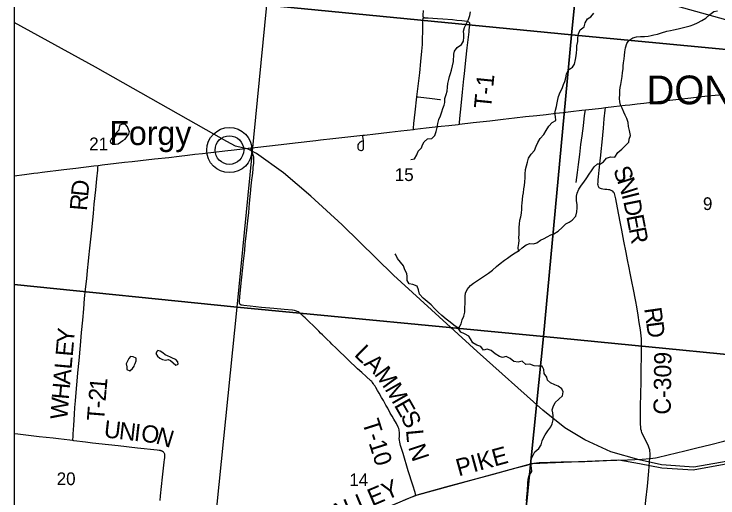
# Model space of a CAD drawing. Extents: x 831 to 1552, y 430 to 870.
# Drawn here: x 1250.77 to 1297.11, y 696.04 to 727.92 of the extents above; entities that cross this region are included whole.
import ezdxf

# ---------------------------------------------------------------- set-up
doc = ezdxf.new("R2010")
doc.units = 0
for name, color, linetype in [('GM_X_Corporation', 7, 'Continuous'), ('GM_X_Corporation_Text', 7, 'Continuous'), ('GM_X_County_Road', 7, 'Continuous'), ('GM_X_County_Road_Text', 7, 'Continuous'), ('GM_X_Minor_Lake', 7, 'Continuous'), ('GM_X_Minor_River', 7, 'Continuous'), ('GM_X_Rail_Line', 7, 'Continuous'), ('GM_X_Section_Text', 7, 'Continuous'), ('GM_X_Township_Road', 7, 'Continuous'), ('GM_X_Township_Road_Text', 7, 'Continuous'), ('GM_X_Unincorporated', 7, 'Continuous'), ('GM_X_Unincorporated_Location', 7, 'Continuous'), ('GM_X_Unincorporated_Text', 7, 'Continuous'), ('GM_X_US_Route', 7, 'Continuous'), ('SH_Text', 7, 'Continuous')]:
    doc.layers.add(name, color=color, linetype=linetype)

msp = doc.modelspace()

# ---------------------------------------------------------------- linework, layer by layer
at = {"layer": 'GM_X_Corporation'}
msp.add_lwpolyline([(1250.766, 771.115), (1250.766, 667.013)], dxfattribs=at)
for points in [[(1269.535, 749.022), (1289.554, 747.22), (1287.469, 726.554), (1267.407, 728.501)], [(1289.554, 747.22), (1309.391, 745.383), (1307.365, 724.655), (1287.469, 726.554)], [(1250.766, 730.422), (1250.766, 710.102), (1265.456, 708.606), (1267.407, 728.501)], [(1267.407, 728.501), (1287.469, 726.554), (1285.616, 706.68), (1265.456, 708.606)], [(1287.469, 726.554), (1307.365, 724.655), (1305.299, 704.746), (1285.616, 706.68)], [(1250.766, 710.102), (1250.766, 689.618), (1263.383, 688.281), (1265.456, 708.606)], [(1265.456, 708.606), (1285.616, 706.68), (1283.584, 686.544), (1263.383, 688.281)], [(1305.299, 704.746), (1303.37, 684.858), (1283.584, 686.544), (1285.616, 706.68)]]:
    msp.add_lwpolyline(points, close=True, dxfattribs=at)
at = {"layer": 'GM_X_County_Road'}
for points in [[(1292.633, 698.634), (1292.643, 698.745), (1292.641, 698.969), (1292.624, 699.153), (1292.614, 699.213), (1292.583, 699.33), (1292.541, 699.445), (1292.464, 699.613), (1292.324, 699.89), (1292.183, 700.167), (1292.108, 700.339), (1292.068, 700.458), (1292.039, 700.581), (1292.021, 700.706), (1292.007, 700.893), (1292.006, 701.143), (1292.018, 701.889), (1292.037, 703.071), (1292.046, 703.506), (1292.051, 704.128), (1292.06, 704.626), (1292.068, 705.246), (1292.072, 705.675), (1292.084, 706.106), (1292.068, 706.512), (1292.053, 706.719), (1292.002, 707.125), (1291.932, 707.589), (1291.856, 708.077), (1291.771, 708.642), (1291.709, 708.976), (1291.521, 709.889), (1291.458, 710.189), (1291.323, 710.844), (1291.256, 711.205), (1291.155, 711.737), (1291.065, 712.219), (1290.911, 712.967), (1290.775, 713.683), (1290.67, 714.233), (1290.489, 715.163), (1290.381, 715.749), (1290.329, 716.017), (1290.305, 716.097), (1290.279, 716.146), (1290.241, 716.194), (1290.179, 716.247), (1290.122, 716.281), (1290.043, 716.313), (1289.986, 716.33), (1289.905, 716.345), (1289.797, 716.359), (1289.656, 716.369), (1289.534, 716.386), (1289.433, 716.411), (1289.367, 716.432), (1289.297, 716.477), (1289.242, 716.557), (1289.214, 716.637), (1289.207, 716.721), (1289.214, 716.854), (1289.228, 716.99), (1289.249, 717.192), (1289.269, 717.411), (1289.289, 717.637), (1289.355, 718.243), (1289.392, 718.621), (1289.415, 718.861), (1289.478, 719.479), (1289.567, 720.408), (1289.625, 721.027), (1289.68, 721.584), (1289.697, 721.76)], [(1292.633, 698.634), (1292.832, 698.659), (1293.002, 698.688), (1293.111, 698.71), (1293.836, 698.882), (1294.929, 699.15), (1295.727, 699.34), (1296.648, 699.564), (1297.492, 699.772), (1298.005, 699.907), (1298.324, 700.001), (1298.721, 700.132), (1300.531, 700.794), (1301.831, 701.285), (1302.769, 701.643), (1303.599, 701.948), (1304.36, 702.232), (1305.159, 702.509)], [(1277.227, 696.204), (1277.316, 696.238), (1277.703, 696.356), (1279.193, 696.763), (1280.741, 697.188), (1282.234, 697.593), (1283.819, 698.019), (1284.447, 698.185), (1284.764, 698.269), (1285.018, 698.323), (1285.168, 698.344), (1285.342, 698.364), (1286.793, 698.409), (1287.917, 698.443), (1288.342, 698.451), (1289.764, 698.499), (1291.153, 698.547), (1292.125, 698.592), (1292.633, 698.634)], [(1261.024, 687.746), (1261.052, 687.764), (1261.356, 687.956), (1263.589, 689.303), (1264.173, 689.657), (1264.599, 689.912), (1266.889, 691.283), (1267.798, 691.821), (1268.765, 692.395), (1269.721, 692.957), (1270.11, 693.177), (1270.355, 693.302), (1270.714, 693.465), (1271.511, 693.812), (1273.397, 694.61), (1274.483, 695.072), (1276.029, 695.719), (1276.702, 695.999), (1276.91, 696.084), (1277.227, 696.204)]]:
    msp.add_lwpolyline(points, dxfattribs=at)
at = {"layer": 'GM_X_Minor_Lake'}
for points in [[(1258.33, 720.254), (1258.23, 720.496), (1258.095, 720.634), (1257.913, 720.659), (1257.73, 720.593), (1257.675, 720.442), (1257.657, 720.282), (1257.519, 720.109), (1257.463, 719.935), (1257.347, 719.785), (1257.172, 719.726), (1257.094, 719.552)], [(1257.094, 719.552), (1257.116, 719.469), (1257.281, 719.353), (1257.448, 719.358), (1257.616, 719.379), (1257.769, 719.491), (1257.922, 719.581), (1258.091, 719.677), (1258.199, 719.836), (1258.33, 720.009), (1258.363, 720.175), (1258.33, 720.254)], [(1258.794, 705.257), (1258.605, 705.343), (1258.438, 705.367), (1258.33, 705.217), (1258.237, 705.051), (1258.144, 704.87), (1258.187, 704.679), (1258.192, 704.497), (1258.389, 704.419), (1258.573, 704.561), (1258.666, 704.727), (1258.698, 704.811)], [(1260.182, 705.712), (1260.097, 705.561), (1260.209, 705.385), (1260.359, 705.246), (1260.548, 705.153), (1260.73, 705.128), (1260.912, 705.156), (1261.071, 705.094), (1261.417, 704.786), (1261.518, 704.83)], [(1261.518, 704.83), (1261.57, 704.852), (1261.549, 705.012), (1261.414, 705.158), (1261.247, 705.228), (1261.059, 705.306), (1260.87, 705.4), (1260.711, 705.462), (1260.561, 705.601), (1260.38, 705.702), (1260.221, 705.757), (1260.182, 705.712)], [(1258.698, 704.811), (1258.729, 704.893), (1258.799, 705.067), (1258.794, 705.257)]]:
    msp.add_lwpolyline(points, dxfattribs=at)
at = {"layer": 'GM_X_Minor_River'}
for points in [[(1279.635, 724.514), (1279.707, 724.794), (1279.713, 725.272), (1279.753, 725.477), (1279.939, 725.718), (1280.222, 725.92), (1280.362, 726.146), (1280.38, 726.404), (1280.368, 726.594), (1280.355, 726.791), (1280.426, 727.041), (1280.567, 727.351), (1280.676, 727.57), (1280.77, 727.827), (1280.819, 728.062)], [(1293.398, 726.677), (1293.741, 726.787), (1293.985, 726.837), (1294.176, 726.888), (1294.488, 726.937), (1294.747, 727.003), (1295.021, 727.076), (1295.288, 727.156), (1295.525, 727.237), (1295.769, 727.348), (1296.045, 727.489), (1296.32, 727.66), (1296.581, 727.893), (1296.835, 728.087), (1297.078, 728.13)], [(1283.987, 712.327), (1283.962, 712.533), (1284.01, 712.798), (1284.013, 712.995), (1284.008, 713.208), (1284.018, 713.398), (1284.013, 713.648), (1284.024, 713.891), (1284.042, 714.088), (1284.075, 714.331), (1284.123, 714.558), (1284.164, 714.801), (1284.191, 715.074), (1284.201, 715.279), (1284.211, 715.469), (1284.236, 715.704), (1284.262, 715.946), (1284.302, 716.143), (1284.336, 716.416), (1284.369, 716.636), (1284.387, 716.871), (1284.406, 717.137), (1284.416, 717.372), (1284.443, 717.676), (1284.571, 718.16), (1284.627, 718.433), (1284.813, 718.681), (1285.021, 718.937), (1285.146, 719.224), (1285.248, 719.458), (1285.403, 719.715), (1285.641, 719.978), (1285.797, 720.242), (1285.975, 720.536), (1286.198, 720.769), (1286.436, 720.918), (1286.408, 721.176), (1286.365, 721.367), (1286.406, 721.579), (1286.47, 721.836), (1286.518, 722.064), (1286.574, 722.291), (1286.615, 722.495), (1286.725, 722.775), (1286.842, 723.024), (1286.944, 723.274), (1287.022, 723.47), (1287.101, 723.72), (1287.135, 723.978), (1287.275, 724.242), (1287.543, 724.414), (1287.667, 724.61), (1287.739, 724.92), (1287.772, 725.17), (1287.798, 725.375), (1287.808, 725.588), (1287.826, 725.838), (1287.875, 726.111), (1287.893, 726.346), (1287.927, 726.627), (1288.044, 726.876), (1288.298, 727.071), (1288.377, 727.343), (1288.517, 727.6), (1288.747, 727.742), (1288.932, 727.99)], [(1280.022, 707.209), (1280.207, 707.504), (1280.279, 707.769), (1280.381, 708.026), (1280.452, 708.276), (1280.448, 708.557), (1280.46, 708.868), (1280.47, 709.111), (1280.465, 709.324), (1280.491, 709.528), (1280.592, 709.77), (1280.808, 710.041), (1281.015, 710.183), (1281.276, 710.377), (1281.475, 710.504), (1281.743, 710.668), (1281.996, 710.84), (1282.264, 711.049), (1282.525, 711.281), (1282.771, 711.491), (1283.047, 711.708), (1283.262, 711.827), (1283.507, 712.029), (1283.76, 712.193), (1284.012, 712.342), (1284.212, 712.522), (1284.473, 712.717), (1284.717, 712.797), (1284.975, 712.787), (1285.181, 712.853), (1285.419, 713.017), (1285.663, 713.135), (1285.87, 713.239), (1286.114, 713.373), (1286.305, 713.439), (1286.596, 713.626), (1286.85, 713.866), (1287.096, 714.106), (1287.31, 714.217), (1287.517, 714.344), (1287.748, 714.607), (1287.812, 714.887), (1287.838, 715.16), (1287.833, 715.358), (1287.806, 715.631), (1287.802, 715.912), (1287.835, 716.117), (1287.952, 716.389), (1288.115, 716.645), (1288.277, 716.841), (1288.47, 717.12), (1288.625, 717.368), (1288.773, 717.602), (1288.966, 717.866), (1289.181, 718.061), (1289.378, 718.058), (1289.57, 718.185), (1289.778, 718.433), (1290.037, 718.506), (1290.311, 718.503), (1290.512, 718.789), (1290.773, 719.022), (1291.019, 719.269), (1291.235, 719.487), (1291.26, 719.684), (1291.354, 719.918), (1291.29, 720.246), (1291.217, 720.52), (1291.197, 720.771), (1291.117, 721.038), (1291.006, 721.252), (1290.917, 721.458), (1290.799, 721.71), (1290.703, 721.946), (1290.652, 722.144), (1290.624, 722.35), (1290.643, 722.638), (1290.654, 722.889), (1290.672, 723.093), (1290.712, 723.283), (1290.761, 723.533), (1290.794, 723.806), (1290.821, 724.071), (1290.862, 724.322), (1290.879, 724.511), (1290.897, 724.716), (1290.931, 724.982), (1290.964, 725.186), (1290.989, 725.437), (1291.031, 725.702), (1291.118, 725.974), (1291.242, 726.17), (1291.51, 726.365), (1291.746, 726.43), (1292.013, 726.45), (1292.278, 726.432), (1292.514, 726.459), (1292.705, 726.51), (1292.895, 726.546), (1293.139, 726.596), (1293.398, 726.677)], [(1276.892, 718.341), (1277.121, 718.392), (1277.283, 718.64), (1277.378, 718.897), (1277.593, 719.107), (1277.656, 719.304), (1277.765, 719.5), (1277.995, 719.703), (1278.261, 719.73), (1278.469, 719.91), (1278.563, 720.182), (1278.62, 720.455), (1278.661, 720.705), (1278.74, 720.97), (1278.834, 721.212), (1278.921, 721.484), (1279, 721.696), (1279.079, 721.915), (1279.119, 722.105), (1279.122, 722.363), (1279.217, 722.627), (1279.288, 722.832), (1279.306, 723.097), (1279.324, 723.34), (1279.388, 723.605), (1279.444, 723.802), (1279.507, 723.999), (1279.556, 724.226), (1279.635, 724.514)], [(1285.529, 704.724), (1285.286, 704.719), (1285.005, 704.745), (1284.725, 704.862), (1284.467, 704.842), (1284.219, 705.043), (1283.952, 704.985), (1283.664, 705.026), (1283.423, 705.234), (1283.167, 705.359), (1282.915, 705.286), (1282.718, 705.349), (1282.447, 705.542), (1282.176, 705.75), (1281.919, 705.837), (1281.683, 705.771), (1281.488, 706.024), (1281.231, 706.103), (1280.974, 706.258), (1280.811, 706.518), (1280.707, 706.709), (1280.427, 706.849), (1280.178, 706.966), (1280.007, 707.233), (1279.728, 707.434), (1279.479, 707.612), (1279.216, 707.82), (1278.923, 708.051), (1278.682, 708.289), (1278.465, 708.504), (1278.217, 708.765), (1277.969, 708.988), (1277.691, 709.212), (1277.466, 709.465), (1277.386, 709.755), (1277.298, 709.991), (1277.026, 710.093), (1276.776, 710.149), (1276.649, 710.371), (1276.652, 710.621), (1276.624, 710.819), (1276.498, 711.071), (1276.41, 711.323), (1276.201, 711.568), (1276.006, 711.821), (1275.895, 712.065), (1275.864, 712.119)], [(1284.508, 695.852), (1284.534, 696.11), (1284.552, 696.33), (1284.577, 696.534), (1284.583, 696.997), (1284.624, 697.278), (1284.681, 697.513), (1284.851, 697.776), (1284.839, 698.027), (1284.781, 698.278), (1284.8, 698.551), (1284.924, 698.808), (1285.057, 699.087), (1285.325, 699.289), (1285.465, 699.538), (1285.537, 699.803), (1285.63, 700), (1285.739, 700.203), (1285.917, 700.467), (1286.103, 700.723), (1286.204, 700.919), (1286.268, 701.184), (1286.256, 701.442), (1286.228, 701.64), (1286.2, 701.838), (1286.256, 702.035), (1286.396, 702.329), (1286.627, 702.554), (1286.872, 702.772), (1286.929, 703.037), (1286.84, 703.228), (1286.599, 703.413), (1286.38, 703.499), (1286.093, 703.624), (1285.882, 703.808), (1285.839, 704.006), (1285.675, 704.228), (1285.64, 704.494), (1285.529, 704.724)]]:
    msp.add_lwpolyline(points, dxfattribs=at)
at = {"layer": 'GM_X_Rail_Line'}
for points in [[(1298.165, 698.538), (1295.52, 698.073), (1293.393, 698.231), (1291.914, 698.547), (1290.066, 699.084), (1288.334, 699.86), (1287.035, 700.657), (1285.578, 701.832), (1281.266, 705.686), (1275.746, 710.712), (1272.364, 714.04), (1270.301, 715.92), (1268.501, 717.45), (1266.727, 718.726), (1266.168, 719.011), (1265.343, 719.228), (1264.784, 719.514), (1263.408, 720.296), (1256.132, 724.433), (1250.766, 727.368)], [(1250.766, 679.957), (1255.444, 683.813), (1257.495, 685.358), (1259.895, 687.02), (1261.608, 688.118), (1265.466, 690.461), (1268.571, 692.318), (1270.198, 693.26), (1277.176, 696.209), (1284.864, 698.305), (1290.582, 698.552), (1291.934, 698.299), (1293.404, 698.016), (1295.482, 697.897), (1297.508, 698.271), (1299.512, 698.644), (1302.371, 699.157), (1309.027, 700.546), (1335.38, 705.567), (1347.114, 707.619), (1348.184, 707.837)]]:
    msp.add_lwpolyline(points, dxfattribs=at)
at = {"layer": 'GM_X_Township_Road'}
for points in [[(1277.735, 727.69), (1277.718, 727.709), (1277.703, 727.732), (1277.695, 727.758), (1277.692, 727.786), (1277.693, 727.846), (1277.716, 728.153)], [(1277.294, 722.466), (1277.334, 722.819), (1277.472, 724.056), (1277.548, 724.799), (1277.614, 725.48), (1277.651, 725.914), (1277.666, 726.224), (1277.677, 726.846), (1277.683, 727.406), (1277.689, 727.548), (1277.706, 727.619), (1277.735, 727.69)], [(1280.092, 720.666), (1280.099, 720.755), (1280.122, 721.048), (1280.202, 721.877), (1280.288, 722.78), (1280.384, 723.644), (1280.421, 723.991), (1280.508, 724.878), (1280.602, 725.701), (1280.722, 726.755), (1280.739, 726.889), (1280.767, 727.186), (1280.771, 727.256), (1280.77, 727.287), (1280.765, 727.317), (1280.751, 727.345), (1280.733, 727.369), (1280.707, 727.39), (1280.671, 727.409), (1280.582, 727.429), (1280.422, 727.453), (1280.243, 727.476), (1279.922, 727.506), (1279.625, 727.536), (1279.006, 727.579), (1278.636, 727.607), (1278.336, 727.627), (1278.026, 727.651), (1277.839, 727.658), (1277.808, 727.661), (1277.781, 727.667), (1277.735, 727.69)], [(1277.055, 720.321), (1277.064, 720.411), (1277.094, 720.716), (1277.18, 721.459), (1277.294, 722.466)], [(1277.294, 722.466), (1277.38, 722.457), (1278.3, 722.357), (1278.789, 722.293), (1278.849, 722.284)], [(1287.776, 716.82), (1287.86, 717.493), (1287.926, 718.008), (1288.01, 718.666), (1288.09, 719.336), (1288.163, 719.895), (1288.248, 720.566), (1288.332, 721.243), (1288.365, 721.489), (1288.381, 721.605)], [(1273.749, 719.564), (1273.642, 719.522), (1273.577, 719.489), (1273.518, 719.454), (1273.477, 719.418), (1273.436, 719.369), (1273.408, 719.312), (1273.396, 719.257), (1273.389, 719.198), (1273.39, 719.138), (1273.405, 719.083), (1273.424, 719.038), (1273.45, 719.004), (1273.488, 718.974), (1273.539, 718.949), (1273.586, 718.941), (1273.646, 718.939), (1273.703, 718.96), (1273.748, 719.001), (1273.774, 719.056), (1273.78, 719.117), (1273.782, 719.244), (1273.777, 719.296), (1273.765, 719.597), (1273.756, 719.717), (1273.738, 719.849), (1273.727, 719.937)], [(1277.227, 696.204), (1277.164, 696.407), (1277.017, 696.882), (1276.722, 697.832), (1276.38, 698.963), (1276.215, 699.498), (1276.156, 699.709), (1276.134, 699.857), (1276.131, 699.954), (1276.136, 700.062), (1276.145, 700.227), (1276.139, 700.384), (1276.128, 700.469), (1276.116, 700.538), (1276.094, 700.623), (1276.065, 700.703), (1275.945, 700.934), (1275.763, 701.236), (1275.666, 701.418), (1275.538, 701.634), (1275.364, 701.948), (1275.242, 702.162), (1275.082, 702.452), (1274.966, 702.651), (1274.806, 702.936), (1274.701, 703.116), (1274.581, 703.318), (1274.53, 703.409), (1274.484, 703.48), (1274.439, 703.548), (1274.348, 703.663), (1274.31, 703.705), (1274.256, 703.762), (1273.94, 704.049), (1273.662, 704.297), (1273.385, 704.547), (1273.203, 704.716), (1272.942, 704.973), (1272.544, 705.358), (1272.195, 705.695), (1272.128, 705.759), (1272.04, 705.844), (1271.976, 705.906), (1271.694, 706.178), (1271.569, 706.297), (1271.374, 706.488), (1271.07, 706.783), (1270.952, 706.902), (1270.827, 707.027), (1270.426, 707.415), (1270.249, 707.592), (1269.921, 707.91), (1269.824, 708.001), (1269.729, 708.086), (1269.585, 708.223), (1269.53, 708.266), (1269.47, 708.302), (1269.413, 708.33), (1269.354, 708.353), (1269.293, 708.371), (1269.232, 708.385), (1269.108, 708.405), (1268.55, 708.46), (1267.868, 708.523), (1267.063, 708.595), (1266.32, 708.666), (1265.895, 708.71), (1265.776, 708.731), (1265.72, 708.747), (1265.671, 708.776), (1265.635, 708.816), (1265.61, 708.864), (1265.604, 708.921), (1265.607, 708.979), (1265.632, 709.288), (1265.703, 709.968), (1265.768, 710.586), (1265.834, 711.204), (1265.875, 711.637), (1265.95, 712.351), (1265.992, 712.75), (1266.028, 713.122), (1266.09, 713.678), (1266.151, 714.297), (1266.212, 714.853), (1266.275, 715.471), (1266.339, 716.089), (1266.386, 716.609), (1266.428, 717.008), (1266.454, 717.262), (1266.497, 717.686), (1266.517, 717.84), (1266.544, 718.068), (1266.553, 718.192), (1266.56, 718.316), (1266.56, 718.379), (1266.555, 718.443), (1266.545, 718.505), (1266.53, 718.567), (1266.492, 718.687), (1266.408, 718.92), (1266.369, 719.039), (1266.346, 719.106)], [(1254.635, 699.814), (1254.638, 699.88), (1254.646, 700.069), (1254.659, 700.233), (1254.68, 700.544), (1254.697, 700.813), (1254.718, 701.196), (1254.739, 701.57), (1254.768, 701.991), (1254.809, 702.436), (1254.876, 703.24), (1254.918, 703.735), (1254.967, 704.292), (1255.043, 705.095), (1255.135, 706.084), (1255.213, 706.949), (1255.286, 707.753), (1255.353, 708.494), (1255.411, 709.174), (1255.473, 709.792), (1255.546, 710.471), (1255.607, 711.026), (1255.669, 711.642), (1255.693, 711.889), (1255.761, 712.506), (1255.863, 713.492), (1255.988, 714.789), (1256.045, 715.406), (1256.14, 716.332), (1256.211, 717.074), (1256.271, 717.629), (1256.29, 717.814), (1256.305, 717.953)], [(1254.635, 699.814), (1254.44, 699.838), (1253.684, 699.928), (1253.33, 699.97), (1252.424, 700.075), (1251.711, 700.155), (1251.008, 700.237), (1250.766, 700.266)], [(1260.381, 695.879), (1260.416, 696.178), (1260.546, 697.414), (1260.657, 698.405), (1260.677, 698.575), (1260.688, 698.677), (1260.691, 698.711), (1260.696, 698.786), (1260.696, 698.818), (1260.694, 698.869), (1260.688, 698.903), (1260.682, 698.934), (1260.674, 698.958), (1260.655, 698.996), (1260.634, 699.026), (1260.617, 699.048), (1260.588, 699.076), (1260.567, 699.092), (1260.538, 699.109), (1260.518, 699.119), (1260.499, 699.128), (1260.47, 699.139), (1260.436, 699.148), (1260.398, 699.156), (1260.352, 699.164), (1260.314, 699.17), (1260.184, 699.189), (1258.891, 699.322), (1257.619, 699.462), (1256.981, 699.538), (1255.919, 699.657), (1255.469, 699.712), (1254.701, 699.806), (1254.635, 699.814)], [(1290.94, 680.602), (1290.959, 681.116), (1291.008, 681.922), (1291.041, 682.355), (1291.127, 683.282), (1291.209, 684.147), (1291.272, 684.828), (1291.334, 685.445), (1291.393, 686.001), (1291.437, 686.433), (1291.548, 687.483), (1291.653, 688.658), (1291.699, 689.153), (1291.802, 690.266), (1291.952, 691.749), (1292.277, 694.962), (1292.37, 695.889), (1292.462, 696.816), (1292.555, 697.805), (1292.607, 698.423), (1292.633, 698.634)]]:
    msp.add_lwpolyline(points, dxfattribs=at)
at = {"layer": 'GM_X_Unincorporated'}
for radius in [1.488, 0.943]:
    msp.add_circle((1264.941, 718.96), radius, dxfattribs=at)
at = {"layer": 'GM_X_Unincorporated_Location'}
msp.add_line((1264.941, 718.96), (1264.941, 718.96), dxfattribs=at)
at = {"layer": 'GM_X_US_Route'}
for points in [[(1266.346, 719.106), (1266.625, 719.138), (1268.355, 719.328), (1269.281, 719.435), (1270.639, 719.588), (1270.948, 719.626), (1271.75, 719.72), (1272.738, 719.832), (1273.727, 719.937), (1273.835, 719.95), (1274.007, 719.972), (1274.378, 720.015), (1275.489, 720.146), (1276.231, 720.227), (1277.055, 720.321), (1277.158, 720.333), (1277.899, 720.418), (1278.887, 720.535), (1279.382, 720.586), (1280, 720.655), (1280.092, 720.666), (1280.988, 720.771), (1282.1, 720.897), (1282.964, 720.998), (1283.706, 721.082), (1284.447, 721.165), (1285.189, 721.244), (1285.807, 721.313), (1286.425, 721.387), (1286.918, 721.443), (1287.413, 721.499), (1288.154, 721.582), (1288.381, 721.605), (1288.834, 721.652), (1289.451, 721.73), (1289.697, 721.76), (1290.254, 721.826), (1290.995, 721.908), (1291.304, 721.942), (1291.798, 721.998), (1292.231, 722.049), (1292.724, 722.108), (1293.343, 722.174), (1294.33, 722.291), (1295.319, 722.401), (1296.431, 722.528), (1297.421, 722.632)], [(1257.483, 718.093), (1258.043, 718.16), (1258.537, 718.215), (1259.094, 718.27), (1260.02, 718.382), (1260.946, 718.48), (1261.625, 718.565), (1262.18, 718.626), (1262.675, 718.68), (1263.169, 718.736), (1263.889, 718.819)], [(1263.889, 718.819), (1263.909, 718.821), (1264.65, 718.905), (1265.267, 718.98), (1266.346, 719.106)], [(1252.338, 717.463), (1252.615, 717.497), (1254.034, 717.672), (1254.835, 717.774), (1256.007, 717.918), (1256.305, 717.953)], [(1256.305, 717.953), (1256.562, 717.983), (1257.483, 718.093)], [(1250.766, 717.266), (1251.444, 717.352), (1252.061, 717.429), (1252.338, 717.463)]]:
    msp.add_lwpolyline(points, dxfattribs=at)
at = {"layer": 'SH_Text'}
msp.add_lwpolyline([(1309.717, 724.179), (1213.915, 750.822), (1213.915, 760.257)], close=True, dxfattribs=at)

# ---------------------------------------------------------------- texts
at = {"layer": 'GM_X_Corporation_Text'}
msp.add_text('DONNELSVILLE', height=1.89394, rotation=0, dxfattribs=at).set_placement((1292.409, 721.976))
at = {"layer": 'GM_X_County_Road_Text'}
for s, height, rotation, p in [('S', 1.136, 291.0126, (1290.188, 717.654)), ('N', 1.136, 288.0289, (1290.457, 716.953)), ('I', 1.136, 284.1148, (1290.761, 716.021)), ('D', 1.136, 281.3746, (1290.872, 715.583)), ('E', 1.136, 280.9826, (1291.069, 714.605)), ('R', 1.136, 280.9797, (1291.23, 713.77)), ('R', 1.136, 278.1969, (1292.246, 708.522)), ('D', 1.136, 277.6507, (1292.379, 707.601)), ('C-309', 1.1364, 89.1905, (1293.995, 701.52)), ('PIKE', 1.1364, 15.3088, (1280.037, 697.457)), ('VALLEY', 1.1364, 22.8831, (1270.911, 694.036))]:
    msp.add_text(s, height=height, rotation=rotation, dxfattribs=at).set_placement(p)
at = {"layer": 'GM_X_Section_Text'}
for s, height, p in [('21', 0.8371, (1255.712, 718.949)), ('15', 0.8371, (1275.829, 716.92)), ('9', 0.837, (1296.121, 715.01)), ('20', 0.8371, (1253.571, 696.885)), ('14', 0.8371, (1272.837, 696.816))]:
    msp.add_text(s, height=height, rotation=0, dxfattribs=at).set_placement(p)
at = {"layer": 'GM_X_Township_Road_Text'}
for s, height, rotation, p in [('T-1', 1.1364, 84.2879, (1282.169, 721.649)), ('D', 1.136, 84.0882, (1255.636, 715.857)), ('R', 1.136, 85.1506, (1255.558, 714.933)), ('Y', 1.136, 84.9141, (1254.698, 706.178)), ('E', 1.136, 84.9148, (1254.623, 705.332)), ('L', 1.136, 315.9198, (1273.107, 705.438)), ('A', 1.136, 317.5126, (1273.743, 704.823)), ('L', 1.136, 84.9148, (1254.548, 704.485)), ('A', 1.136, 84.9152, (1254.459, 703.489)), ('M', 1.136, 305.9442, (1274.44, 704.193)), ('H', 1.136, 84.919, (1254.37, 702.493)), ('1', 1.136, 84.8463, (1256.848, 703.076)), ('M', 1.136, 299.7984, (1275.146, 703.221)), ('2', 1.136, 85.379, (1256.791, 702.381)), ('W', 1.136, 85.7603, (1254.274, 701.184)), ('E', 1.136, 299.6859, (1275.759, 702.152)), ('-', 1.136, 85.4363, (1256.754, 701.916)), ('T', 1.136, 85.4526, (1256.687, 701.069)), ('S', 1.136, 297.0825, (1276.173, 701.425)), ('U', 1.136, 353.438, (1256.639, 700.037)), ('T-10', 1.1364, 287.5263, (1273.672, 701.036)), ('N', 1.136, 353.4361, (1257.632, 699.922)), ('I', 1.136, 353.4372, (1258.626, 699.808)), ('O', 1.136, 353.4086, (1259.089, 699.755)), ('N', 1.136, 342.9354, (1260.029, 699.651)), ('L', 1.136, 275.3735, (1276.565, 700.509)), ('N', 1.136, 288.4749, (1276.703, 699.386))]:
    msp.add_text(s, height=height, rotation=rotation, dxfattribs=at).set_placement(p)
at = {"layer": 'GM_X_Unincorporated_Text'}
msp.add_text('Forgy', height=1.5795, rotation=0, dxfattribs=at).set_placement((1257.037, 719.291))

doc.saveas('drawing.dxf')
